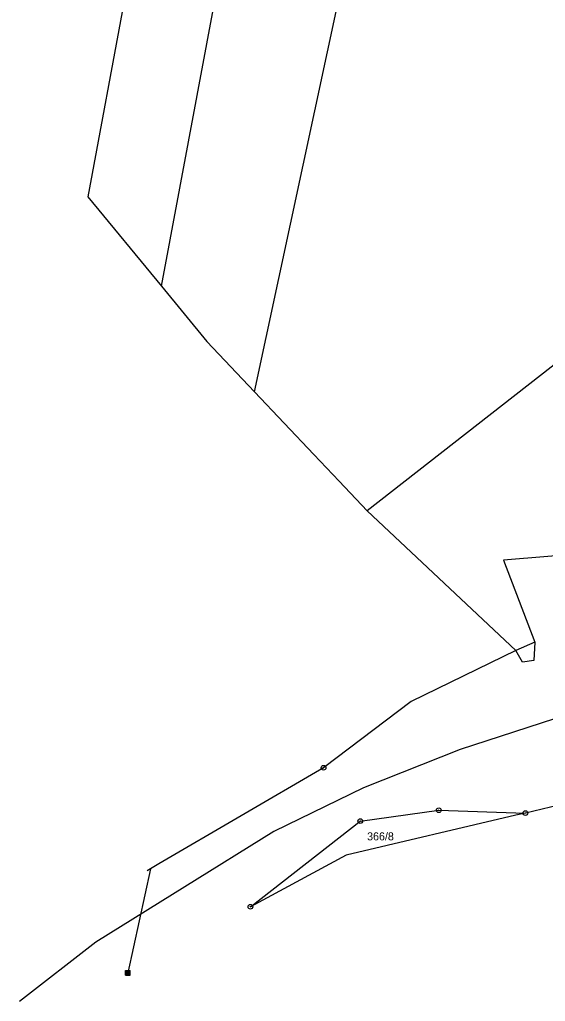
# Model space of a CAD drawing. Extents: x -776701 to -776081, y -974398 to -973771.
# Drawn here: x -776698.3 to -776586.6, y -974396.3 to -974187.7 of the extents above; entities that cross this region are included whole.
import ezdxf

# ---------------------------------------------------------------- set-up
doc = ezdxf.new("R2010")
doc.units = 0
for name, color, linetype in [('Hranice parcel', 7, 'Continuous'), ('Parcelní čísla', 7, 'Continuous'), ('Poz předměty', 7, 'Continuous'), ('Vnitřní kresba', 7, 'Continuous'), ('Značky bodu BP', 7, 'Continuous')]:
    doc.layers.add(name, color=color, linetype=linetype)

msp = doc.modelspace()

# ---------------------------------------------------------------- linework, layer by layer
at = {"layer": 'Hranice parcel'}
for p, q in [((-776635.77, -974280.07), (-776630.38, -974285.76)), ((-776630.38, -974285.76), (-776624.42, -974292.05)), ((-776624.42, -974292.05), (-776592.85, -974321.75)), ((-776633.71, -974346.66), (-776668.7, -974367.1)), ((-776625.91, -974357.98), (-776609.22, -974355.67)), ((-776609.22, -974355.67), (-776590.8, -974356.28)), ((-776583.73, -974354.62), (-776590.8, -974356.28)), ((-776649.26, -974376.19), (-776625.91, -974357.98)), ((-776590.8, -974356.28), (-776592.81, -974356.75))]:
    msp.add_line(p, q, dxfattribs=at)
for points in [[(-776683.78, -974225.34), (-776668.16, -974244.33), (-776658.51, -974256.07), (-776648.38, -974266.76), (-776635.77, -974280.07)], [(-776535.24, -974237.89), (-776540.45, -974226.46), (-776624.42, -974292.05)], [(-776518.5, -974306.54), (-776551.36, -974303.43), (-776577.49, -974301.09), (-776595.43, -974302.58), (-776588.8, -974320), (-776592.85, -974321.75)], [(-776592.85, -974321.75), (-776615.12, -974332.55), (-776633.71, -974346.66)], [(-776592.81, -974356.75), (-776628.94, -974365.22), (-776649.26, -974376.19)], [(-776668.7, -974367.1), (-776670.47, -974368.14), (-776671.23, -974368.59)]]:
    msp.add_lwpolyline(points, dxfattribs=at)
at = {"layer": 'Poz předměty'}
for p, q in [((-776668.16, -974244.33), (-776621.24, -973993.22)), ((-776643.47, -974007.53), (-776683.78, -974225.34)), ((-776648.38, -974266.76), (-776621.57, -974141.84)), ((-776576.01, -974333.45), (-776604.66, -974342.76)), ((-776604.66, -974342.76), (-776625.24, -974350.93)), ((-776625.24, -974350.93), (-776644.25, -974360.23)), ((-776644.25, -974360.23), (-776682.14, -974383.72)), ((-776670.47, -974368.14), (-776675.29, -974390.25)), ((-776682.14, -974383.72), (-776698.31, -974396.29)), ((-776675.79, -974389.75), (-776674.79, -974389.75)), ((-776675.79, -974390.75), (-776675.79, -974389.75)), ((-776675.79, -974389.95), (-776674.79, -974389.95)), ((-776675.79, -974390.15), (-776674.79, -974390.15)), ((-776675.79, -974390.35), (-776674.79, -974390.35)), ((-776675.79, -974390.55), (-776674.79, -974390.55)), ((-776675.79, -974390.75), (-776674.79, -974390.75)), ((-776675.59, -974390.75), (-776675.59, -974389.75)), ((-776675.39, -974390.75), (-776675.39, -974389.75)), ((-776675.19, -974390.75), (-776675.19, -974389.75)), ((-776674.99, -974390.75), (-776674.99, -974389.75)), ((-776674.79, -974390.75), (-776674.79, -974389.75))]:
    msp.add_line(p, q, dxfattribs=at)
at = {"layer": 'Vnitřní kresba'}
for p, q in [((-776588.8, -974320), (-776589.01, -974323.89)), ((-776591.42, -974324.24), (-776592.85, -974321.75)), ((-776589.01, -974323.89), (-776591.42, -974324.24))]:
    msp.add_line(p, q, dxfattribs=at)
at = {"layer": 'Značky bodu BP'}
for centre, radius in [((-776633.71, -974346.66), 0.5), ((-776633.71, -974346.66), 0.0303), ((-776609.22, -974355.67), 0.5), ((-776609.22, -974355.67), 0.0303), ((-776590.8, -974356.28), 0.5), ((-776625.91, -974357.98), 0.5), ((-776625.91, -974357.98), 0.0303), ((-776590.8, -974356.28), 0.0303), ((-776649.26, -974376.19), 0.5), ((-776649.26, -974376.19), 0.0303)]:
    msp.add_circle(centre, radius, dxfattribs=at)

# ---------------------------------------------------------------- texts
at = {"layer": 'Parcelní čísla'}
msp.add_text('366/8', height=1.7, dxfattribs=at).set_placement((-776624.46, -974362.08))

doc.saveas('drawing.dxf')
